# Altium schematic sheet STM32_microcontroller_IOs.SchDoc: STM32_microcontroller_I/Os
size A4; Date: Not used; ApprovedBy: Not used; CheckedBy: Not used; Author: Not used; CompanyName: STMicroelectronics; DrawnBy: Not used; Engineer: Not used; Organization: Not used; Address1: Not used; Address2: Not used; Address3: Not used; Address4: Not used; DocumentNumber: 3; Revision: Not used; SheetNumber: 3; SheetTotal: 8
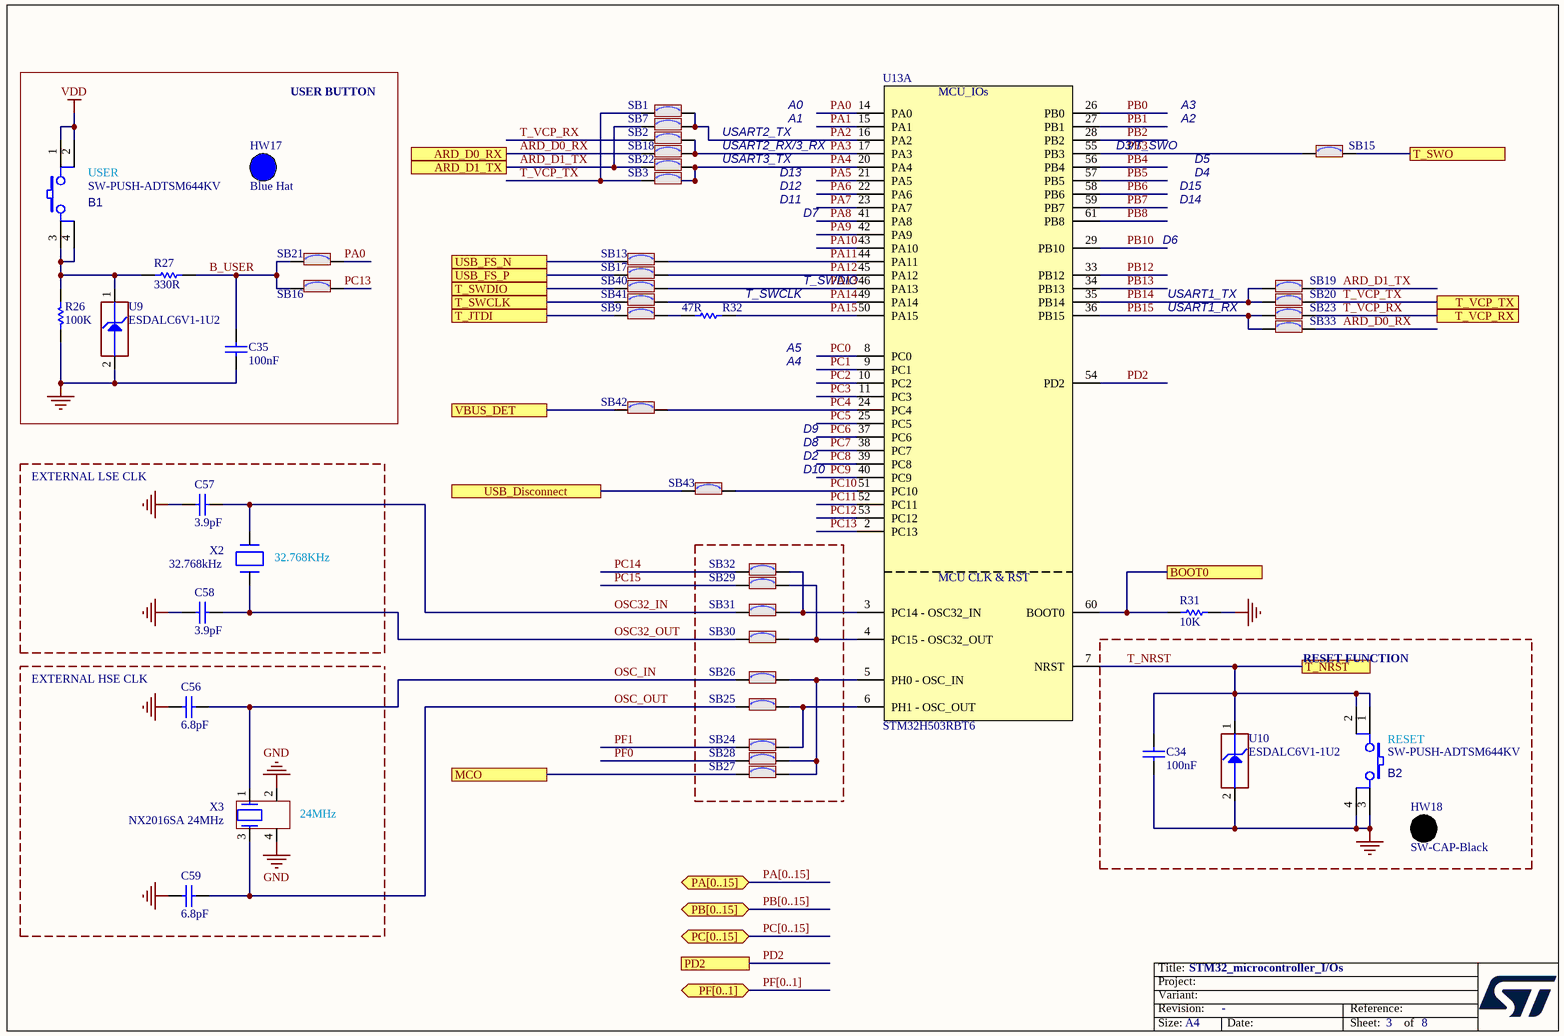
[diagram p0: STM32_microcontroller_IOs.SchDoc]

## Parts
B1  value SW-PUSH-ADTSM644KV  [SWI_APEM_ADTSM644KV_BLACK]  (hidden comment: SW_PUSH_SMD)
B2  value SW-PUSH-ADTSM644KV  [SWI_APEM_ADTSM644KV_BLACK]  (hidden comment: SW_PUSH_SMD)
C34  value 100nF  [C0402]  (hidden comment: Capacitor)
C35  value 100nF  [C0402]  (hidden comment: Capacitor)
C56  value 6.8pF  [C0402]
C57  value 3.9pF  [C0402]  (hidden comment: Capacitor)
C58  value 3.9pF  [C0402]  (hidden comment: Capacitor)
C59  value 6.8pF  [C0402]
HW17  value Blue Hat  (hidden comment: BUTTON_HAT_BLUE)  (mechanical)
HW18  SW-CAP-Black  [N/A]  (mechanical)
R26  value 100K  [R0603]
R27  value 330R  [R0603]
R31  value 10K  [R0603]
R32  value 47R  [R0402]
SB1  (no value)  [SOLDER-BRIDGE_R0603-0R]
SB2  (no value)  [SOLDER-BRIDGE_R0603-0R]
SB3  (no value)  [SOLDER-BRIDGE_R0603-0R]
SB7  (no value)  [SOLDER-BRIDGE_R0603-0R]
SB9  (no value)  [SOLDER-BRIDGE_R0603-0R]
SB13  (no value)  [SOLDER-BRIDGE_R0603-0R]
SB15  (no value)  [SOLDER-BRIDGE_R0603-0R]
SB16  (no value)  [SOLDER-BRIDGE_R0603-0R]
SB17  (no value)  [SOLDER-BRIDGE_R0603-0R]
SB18  (no value)  [SOLDER-BRIDGE_R0603-0R]
SB19  (no value)  [SOLDER-BRIDGE_R0603-0R]
SB20  (no value)  [SOLDER-BRIDGE_R0603-0R]
SB21  (no value)  [SOLDER-BRIDGE_R0603-0R]
SB22  (no value)  [SOLDER-BRIDGE_R0603-0R]
SB23  (no value)  [SOLDER-BRIDGE_R0603-0R]
SB24  (no value)  [SOLDER-BRIDGE_R0603-0R]
SB25  (no value)  [SOLDER-BRIDGE_R0603-0R]
SB26  (no value)  [SOLDER-BRIDGE_R0603-0R]
SB27  (no value)  [SOLDER-BRIDGE_R0603-0R]
SB28  (no value)  [SOLDER-BRIDGE_R0603-0R]
SB29  (no value)  [SOLDER-BRIDGE_R0603-0R]
SB30  (no value)  [SOLDER-BRIDGE_R0603-0R]
SB31  (no value)  [SOLDER-BRIDGE_R0603-0R]
SB32  (no value)  [SOLDER-BRIDGE_R0603-0R]
SB33  (no value)  [SOLDER-BRIDGE_R0603-0R]
SB40  (no value)  [SOLDER-BRIDGE_R0603-0R]
SB41  (no value)  [SOLDER-BRIDGE_R0603-0R]
SB42  (no value)  [SOLDER-BRIDGE_R0603-0R]
SB43  (no value)  [SOLDER-BRIDGE_R0603-0R]
U9  value ESDALC6V1-1U2  [ESD_ST0201]
U10  value ESDALC6V1-1U2  [ESD_ST0201]
U13  value STM32H503RBT6  [ICC_LQFP64_10X10_P050_SOCKET_YAMAICHI_IC149-064-069-B5_NM]  (hidden comment: STM32H503RBH6)  (part A of 2)
X2  value 32.768kHz  [CRY_NX1610SE_2P]  (hidden comment: XTAL_2_PINS)
X3  value NX2016SA 24MHz  [CRY_NX2016SA_4P]

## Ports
ARD_D0_RX, ARD_D1_TX, BOOT0, MCO, PA[0..15] (bidir), PB[0..15] (bidir), PC[0..15] (bidir), PD2, PF[0..1] (bidir), T_JTDI, T_NRST, T_SWCLK, T_SWDIO, T_SWO, T_VCP_RX, T_VCP_TX, USB_Disconnect, USB_FS_N, USB_FS_P, VBUS_DET

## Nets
GND: B2.3 B2.4 C34.1 C35.1 C56.1 C57.1 C58.1 C59.1 R26.1 R31.1 U9.2(GND) U10.2(GND) X3.2 X3.4
VDD: B1.1 B1.2
ARD_D0_RX: SB18.2 SB33.1 ; port ARD_D0_RX
ARD_D1_TX: SB7.2 SB19.1 SB22.2 ; port ARD_D1_TX
B_USER: C35.2 R27.2 SB16.1 SB21.1
BOOT0: R31.2 U13.60(BOOT0) ; port BOOT0
MCO: SB27.1 ; port MCO
OSC32_IN: C57.2 SB31.1 X2.2(X2)
OSC32_OUT: C58.2 SB30.1 X2.1(X1)
OSC_IN: C56.2 SB26.1 X3.1
OSC_OUT: C59.2 SB25.1 X3.3
PA0: SB21.2 U13.14(PA0)
PA1: U13.15(PA1)
PA2: SB1.1 SB7.1 U13.16(PA2)
PA3: SB2.1 SB18.1 U13.17(PA3)
PA4: SB3.1 SB22.1 U13.20(PA4)
PA5: U13.21(PA5)
PA6: U13.22(PA6)
PA7: U13.23(PA7)
PA8: U13.41(PA8)
PA9: U13.42(PA9)
PA10: U13.43(PA10)
PA11: SB13.2 U13.44(PA11)
PA12: SB17.2 U13.45(PA12)
PA13: SB40.2 U13.46(PA13)
PA14: SB41.2 U13.49(PA14)
PA15: R32.2 U13.50(PA15)
PB0: U13.26(PB0)
PB1: U13.27(PB1)
PB2: U13.28(PB2)
PB3: SB15.1 U13.55(PB3)
PB4: U13.56(PB4)
PB5: U13.57(PB5)
PB6: U13.58(PB6)
PB7: U13.59(PB7)
PB8: U13.61(PB8)
PB10: U13.29(PB10)
PB12: U13.33(PB12)
PB13: U13.34(PB13)
PB14: SB19.2 SB20.2 U13.35(PB14)
PB15: SB23.2 SB33.2 U13.36(PB15)
PC0: U13.8(PC0)
PC1: U13.9(PC1)
PC2: U13.10(PC2)
PC3: U13.11(PC3)
PC4: SB42.2 U13.24(PC4)
PC5: U13.25(PC5)
PC6: U13.37(PC6)
PC7: U13.38(PC7)
PC8: U13.39(PC8)
PC9: U13.40(PC9)
PC10: SB43.2 U13.51(PC10)
PC11: U13.52(PC11)
PC12: U13.53(PC12)
PC13: SB16.2 U13.2(PC13)
PC14: SB32.1
PC15: SB29.1
PD2: U13.54(PD2) ; port PD2
PF0: SB28.1
PF1: SB24.1
T_JTDI: SB9.1 ; port T_JTDI
T_NRST: B2.1 B2.2 C34.2 U10.1(IO1) U13.7(NRST) ; port T_NRST
T_SWCLK: SB41.1 ; port T_SWCLK
T_SWDIO: SB40.1 ; port T_SWDIO
T_SWO: SB15.2 ; port T_SWO
T_VCP_RX: SB2.2 SB23.1 ; port T_VCP_RX
T_VCP_TX: SB1.2 SB3.2 SB20.1 ; port T_VCP_TX
USB_Disconnect: SB43.1 ; port USB_Disconnect
USB_FS_N: SB13.1 ; port USB_FS_N
USB_FS_P: SB17.1 ; port USB_FS_P
VBUS_DET: SB42.1 ; port VBUS_DET
NetB1_3: B1.3 B1.4 R26.2 R27.1 U9.1(IO1)
NetR32_1: R32.1 SB9.2
NetSB24_2: SB24.2 SB25.2 U13.6(PH1_-_OSC_OUT)
NetSB26_2: SB26.2 SB27.2 SB28.2 U13.5(PH0_-_OSC_IN)
NetSB29_2: SB29.2 SB30.2 U13.4(PC15_-_OSC32_OUT)
NetSB31_2: SB31.2 SB32.2 U13.3(PC14_-_OSC32_IN)

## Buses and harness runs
bus PA[0..15] = port PA[0..15]
bus PB[0..15] = port PB[0..15]
bus PC[0..15] = port PC[0..15]
bus PF[0..1] = port PF[0..1]

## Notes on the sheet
- USER BUTTON
- A0
- A3
- (near B1) USER
- USART3_TX
- USART2_RX/3_RX
- USART2_TX
- D13
- A1
- D3/T_SWO
- A2
- D4
- D5
- D12
- D11
- D7
- D15
- D6
- D14
- (near R32) T_SWCLK
- (near R32) T_SWDIO
- USART1_RX
- USART1_TX
- A4
- A5
- D8
- D9
- EXTERNAL LSE CLK
- D2
- D10
- (near X2) 32.768KHz
- EXTERNAL HSE CLK
- RESET FUNCTION
- (near B2) RESET
- (near X3) 24MHz

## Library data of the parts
B1 B2 = MCD-02524: Push Button, SPST-NO, 0.05A, 12V SMT, T=7.30mm, changeable caps AKTSC62x; Part_Type: Misc; Part_Preference: Recommended; Manufacturer: APEM INC; Manufacturer_Part_Number: ADTSM644SVTR; Alternate_Manufacturer: DIPTRONICS; Alternate_Manufacturer_Part_Number: DTSM644SVTR
C34 C35 = MCD-00006: Capacitor, MLCC, 100nF, 16V, X7R, +/-10%, 0402, T=0.5mm; Part_Preference: Recommended; Manufacturer: YAGEO; Manufacturer_Part_Number: CC0402KRX7R7BB104; Partial_Alternate_Internal_Part_Number: MCD-03299; Order_Code_RS: 9402047; Component_Country_Of_Origin: China; ShowFields: YES; ID: 2474
C56 C59 = MCD-00674: Capacitor, MLCC, 6.8pF, 50V, NPO, +-0.25pF, 0402, T=0.5mm; Manufacturer_Part_Number: CC0402CRNPO9BN6R8; Manufacturer: YAGEO; Provided_By: SUBCO
C57 C58 = MCD-01602: Capacitor, MLCC, 3.9pF, 50V, NPO, +/-0.1pF, 0402, T=0.5mm; Part_Preference: Recommended; Manufacturer: YAGEO; Manufacturer_Part_Number: CC0402BRNPO9BN3R9; Component_Country_Of_Origin: China; ShowFields: YES; ID: 3702
HW17 = MCD-02136: Switch hat, blue, For KTSC-62B; Part_Type: Misc; Part_Preference: Recommended; Manufacturer: APEM INC; Manufacturer_Part_Number: AKTSC62B; Order_Code_RS: 378-6779; Component_Country_Of_Origin: Unknown; ShowFields: YES; ID: 4236
HW18 = MCD-02526: Black round cap for ADTSM644KV; Part_Type: Mechanical; Part_Preference: Recommended; Manufacturer: APEM INC; Manufacturer_Part_Number: AKTSC62K; Value: SW-CAP-AKTSC62K
R26 = MCD-00223: Resistor,100K,0603,1%,1/10W; Manufacturer_Part_Number: RC0603FR-07100KL; Manufacturer: YAGEO; Provided_By: Subcon; Initial_Board_Reference: MB1319
R27 = MCD-00197: Resistor,330R,0603,1%,1/10W; Manufacturer_Part_Number: RC0603FR-07330RL; Manufacturer: YAGEO; Provided_By: Subcon
R31 = MCD-00220: Resistor,10K,0603,1%,1/10W; Manufacturer_Part_Number: RC0603FR-0710KL; Manufacturer: YAGEO; Provided_By: Subcon; Initial_Board_Reference: MB1319
R32 = MCD-00481: Resistor,47R,0402,1%,1/16W; Manufacturer_Part_Number: RC0402FR-0747RL; Manufacturer: YAGEO; Provided_By: SUBCO; ECCN_US: EAR99; ECCN_EU: NEC
SB1-SB3 SB7 SB9 SB13 SB15-SB33 SB40-SB43 = MCD-00071: Solder Bridge ON; Part_Type: Mechanical; Manufacturer_Part_Number: RC0603JR-070RL; Manufacturer: YAGEO; Provided_By: SUBCO
U9 U10 = MCD-00170: ESD protection 6V1; Part_Type: Diode; Manufacturer: STMICROELECTRONICS; ECCN_US: EAR99; ECCN_EU: NEC; Provided_By: Subcon; Initial_Board_Reference: MB1274
U13 = MCD-02438: MCU, Arm Cortex-M33, 250MHz, 32-bit MCU, 128KB flash, 32KB SRAM; Part_Type: IC; Part_Preference: Recommended; Manufacturer: STMICROELECTRONICS; ShowFields: YES; ID: 4544
X2 = MCD-02291: Crystal, 32.768kHz, 9pF, +/-20ppm, 70KR, 1.6x1mm; Part_Type: Crystal_Osc; Part_Preference: Recommended; Manufacturer: NDK; Manufacturer_Part_Number: NX1610SE-32.768KHZ-EXS00A-MU01499; Component_Country_Of_Origin: Unknown; ShowFields: YES; ID: 4391
X3 = MCD-01036: Crystal 24MHz, 6pF, +-20ppm, 80ohms max, SMD; Part_Type: Crystal_Osc; Manufacturer_Part_Number: NX2016SA 24MHz EXS00A-CS10820; Manufacturer: NDK; BMS_Part_Number: 9157045; ECCN_US: EAR99; ECCN_EU: NEC; Provided_By: SUBCO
